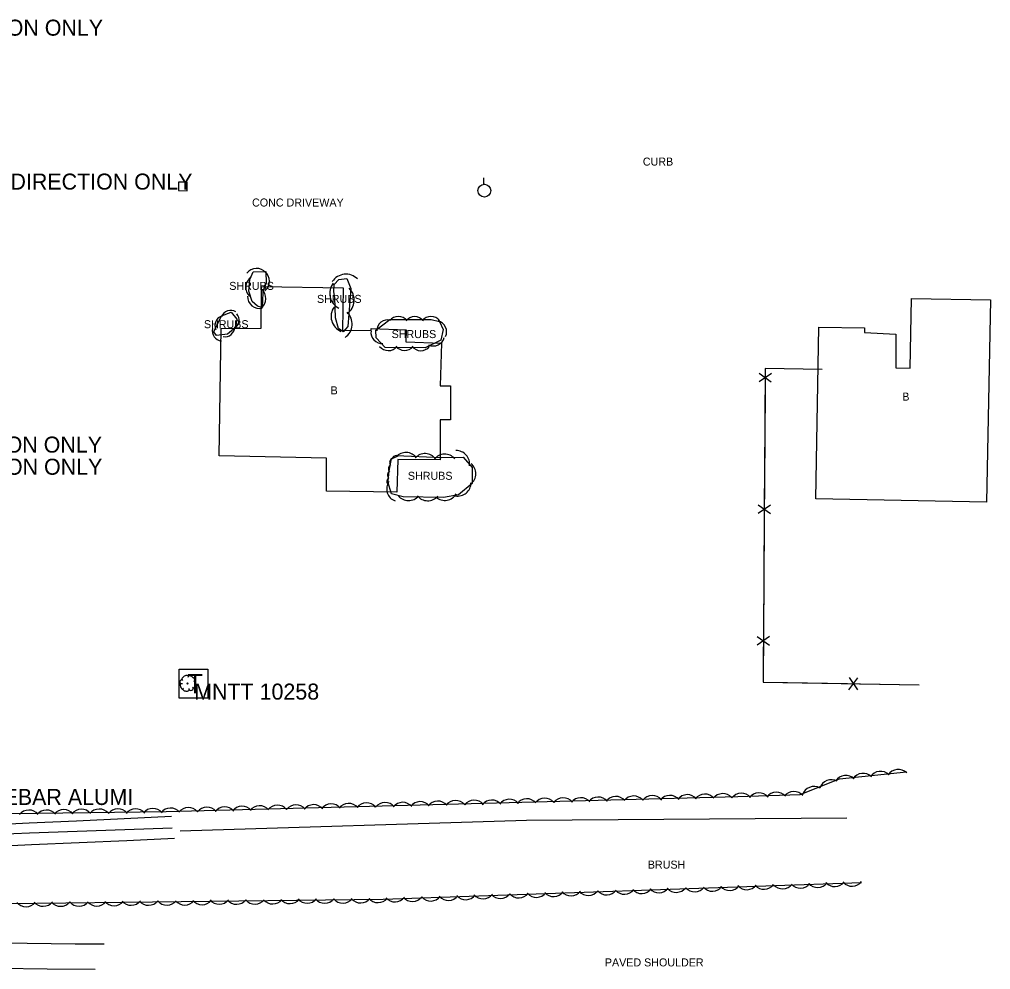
# Model space of a CAD drawing. Extents: x 1802180 to 1804859, y 572524 to 575172.
# Drawn here: x 1804555.9 to 1804859.1, y 573834 to 574130.7 of the extents above; entities that cross this region are included whole.
import ezdxf

# ---------------------------------------------------------------- set-up
doc = ezdxf.new("R2010")
doc.units = 0
for name, color, linetype in [('EX_EDGE_PAVEMENT', 7, 'Continuous'), ('EX_SHOULDER', 7, 'Continuous'), ('S_BUILDING', 7, 'Continuous'), ('S_BUILDING_ANNOT', 7, 'Continuous'), ('S_CURB_ANNOT', 7, 'Continuous'), ('S_DITCHLINE', 7, 'Continuous'), ('S_DRIVEWAY_ANNOT', 7, 'Continuous'), ('S_FENCE', 7, 'Continuous'), ('S_IRON_PIN_ANNOT', 7, 'Continuous'), ('S_MISC_STRUCTURES', 7, 'Continuous'), ('S_SANITARY_SEWER_ANNOT', 7, 'Continuous'), ('S_SHOULDER_ANNOT', 7, 'Continuous'), ('S_STREAM', 7, 'Continuous'), ('S_TELEPHONE_UTILITIES', 7, 'Continuous'), ('S_TELEPHONE_UTILITIES_ANNOT', 7, 'Continuous'), ('S_TREE', 7, 'Continuous'), ('S_TREE_ANNOT', 7, 'Continuous'), ('S_UTILITY_POLE', 7, 'Continuous')]:
    doc.layers.add(name, color=color, linetype=linetype)

msp = doc.modelspace()

# ---------------------------------------------------------------- linework, layer by layer
at = {"layer": 'EX_EDGE_PAVEMENT'}
msp.add_lwpolyline([(1804579.51, 573834.02), (1804564.51, 573834.17), (1804549.51, 573834.32)], dxfattribs=at)
at = {"layer": 'EX_SHOULDER'}
msp.add_lwpolyline([(1804265.55, 573844.85), (1804273.36, 573844.58), (1804288.27, 573844.41), (1804303.25, 573844.37), (1804318.32, 573844.38), (1804333.32, 573844.25), (1804348.29, 573844.14), (1804363.31, 573844.03), (1804378.28, 573843.94), (1804393.31, 573843.88), (1804408.33, 573843.75), (1804423.29, 573843.57), (1804438.35, 573843.38), (1804453.32, 573843.19), (1804468.29, 573843.07), (1804483.29, 573842.96), (1804498.33, 573842.85), (1804513.31, 573842.69), (1804528.29, 573842.53), (1804543.31, 573842.43), (1804558.32, 573842.29), (1804573.31, 573842.11), (1804582.3, 573842.03)], dxfattribs=at)
at = {"layer": 'S_BUILDING'}
for points in [[(1804651.79, 573993.76), (1804618.21, 573994.45), (1804618.82, 574034.25), (1804631.32, 574034.3), (1804631.4, 574047.28), (1804656.97, 574046.95), (1804656.69, 574033.58), (1804665.74, 574033.71), (1804665.69, 574034.22), (1804676.59, 574033.77), (1804676.56, 574029.99), (1804687.61, 574029.63), (1804687.2, 574016.35), (1804690.46, 574016.26), (1804690.44, 574005.65), (1804687.21, 574005.73), (1804687.26, 573993.14), (1804673.98, 573993.25), (1804673.69, 573983.06), (1804651.72, 573983.4), (1804651.79, 573993.76)], [(1804859.1, 574043.14), (1804857.85, 573979.93), (1804804.52, 573981.01), (1804805.42, 574034.61), (1804819.76, 574034.4), (1804819.71, 574032.99), (1804829.54, 574032.44), (1804829.48, 574021.92), (1804833.95, 574021.77), (1804834.43, 574043.6), (1804859.1, 574043.14)]]:
    msp.add_lwpolyline(points, dxfattribs=at)
at = {"layer": 'S_DITCHLINE'}
for points in [[(1804603.31, 573881.86), (1804588.52, 573881.14), (1804573.72, 573880.41), (1804558.93, 573879.69), (1804544.14, 573878.96)], [(1804603.59, 573878.2), (1804588.74, 573877.66), (1804573.9, 573877.12), (1804559.05, 573876.58), (1804544.21, 573876.04)], [(1804604.32, 573874.94), (1804589.41, 573874.27), (1804574.5, 573873.61), (1804559.59, 573872.94), (1804544.68, 573872.27)]]:
    msp.add_lwpolyline(points, dxfattribs=at)
at = {"layer": 'S_FENCE'}
for p, q in [((1804790.65, 574020.19), (1804786.8, 574017.54)), ((1804786.82, 574020.22), (1804790.63, 574017.51)), ((1804790.36, 573979.08), (1804786.51, 573976.43)), ((1804786.53, 573979.11), (1804790.34, 573976.4)), ((1804790.06, 573937.98), (1804786.22, 573935.33)), ((1804786.24, 573938), (1804790.04, 573935.3)), ((1804814.89, 573921.38), (1804817.64, 573925.16)), ((1804814.96, 573925.2), (1804817.57, 573921.33))]:
    msp.add_line(p, q, dxfattribs=at)
for points in [[(1804806.48, 574021.41), (1804788.74, 574021.68), (1804788.05, 573923.77), (1804836.82, 573922.9)], [(1804806.48, 574021.41), (1804788.74, 574021.68), (1804788.74, 574020.73)], [(1804788.71, 574016.99), (1804788.58, 573998.31)], [(1804788.58, 573998.31), (1804788.45, 573979.63)], [(1804788.42, 573975.89), (1804788.29, 573957.2)], [(1804788.29, 573957.2), (1804788.15, 573938.52)], [(1804788.13, 573934.78), (1804788.05, 573923.77), (1804795.72, 573923.63)], [(1804795.72, 573923.63), (1804814.4, 573923.3)], [(1804818.14, 573923.23), (1804836.82, 573922.9)]]:
    msp.add_lwpolyline(points, dxfattribs=at)
at = {"layer": 'S_MISC_STRUCTURES'}
msp.add_lwpolyline([(1804605.58, 574079.93), (1804605.51, 574077.29), (1804608.25, 574077.18), (1804608.28, 574079.85), (1804605.58, 574079.93)], dxfattribs=at)
at = {"layer": 'S_STREAM'}
msp.add_lwpolyline([(1804814.26, 573881.26), (1804714.21, 573880.53), (1804606.01, 573877.25)], dxfattribs=at)
at = {"layer": 'S_TELEPHONE_UTILITIES'}
msp.add_lwpolyline([(1804605.7, 573918.81), (1804605.7, 573927.81), (1804614.7, 573927.81), (1804614.7, 573918.81)], close=True, dxfattribs=at)
at = {"layer": 'S_TREE'}
for p, q in [((1804606.18, 573923.3), (1804606.8, 573923.3)), ((1804606.54, 573924.58), (1804606.82, 573924.26)), ((1804608.64, 573925.7), (1804608.42, 573925.23)), ((1804610.6, 573924.16), (1804610.24, 573924.01)), ((1804606.82, 573921.55), (1804607.08, 573921.93)), ((1804608.85, 573921.4), (1804608.81, 573921.83)), ((1804610.18, 573921.89), (1804609.92, 573922.13))]:
    msp.add_line(p, q, dxfattribs=at)
for points in [[(1804632.83, 574051.97), (1804632.88, 574048.36), (1804631.89, 574045.87), (1804631.77, 574042.58), (1804631.58, 574040.75), (1804630.23, 574041.21), (1804628.54, 574042.59), (1804627.53, 574045.86), (1804627.8, 574049.53), (1804628.84, 574051.86), (1804632.83, 574051.97)], [(1804659.29, 574046.74), (1804658.43, 574034.87), (1804656.9, 574033.13), (1804655.48, 574034.19), (1804654.52, 574037.57), (1804654.38, 574043.87), (1804653.98, 574045.64), (1804654.1, 574047.96), (1804655.64, 574049.54), (1804658.12, 574049.79), (1804659.29, 574046.74)], [(1804618.91, 574038.2), (1804622.02, 574039.27), (1804623.77, 574037.14), (1804623.32, 574034.49), (1804620.88, 574032.46), (1804617.43, 574031.98), (1804616.56, 574033.21), (1804618.91, 574038.2)], [(1804671.49, 574037.05), (1804684.47, 574037.02), (1804687.01, 574036.35), (1804688.18, 574033.94), (1804687.47, 574030.54), (1804682.5, 574028.21), (1804670.11, 574028.25), (1804667.26, 574031.28), (1804667.12, 574033.65), (1804671.49, 574037.05)], [(1804673.49, 573994.53), (1804687.77, 573993.87), (1804694.45, 573994.01), (1804697.24, 573990.82), (1804697.2, 573985.76), (1804692.94, 573982.25), (1804688.32, 573981.43), (1804675.66, 573981.63), (1804672.04, 573982.61), (1804670.86, 573986.31)], [(1804670.87, 573985.44), (1804671.29, 573989.76), (1804672.05, 573993.49), (1804674.08, 573994.48)], [(1804472.42, 573881.72), (1804601.66, 573883.39), (1804780.13, 573888.04), (1804799.65, 573888.65), (1804811.97, 573893.53), (1804832.87, 573895.78)], [(1804818.84, 573861.13), (1804669.43, 573855.95), (1804489.16, 573853.83)]]:
    msp.add_lwpolyline(points, dxfattribs=at)
msp.add_circle((1804608.33, 573923.35), 0.188, dxfattribs=at)
for centre, radius, start, end in [((1804629.91, 574049.1), 3.87, 40.7767, 142.3736), ((1804630.05, 574048.93), 3.87, 310.0027, 51.5996), ((1804657.8, 574046.05), 5.11, 44.9726, 146.5695), ((1804630.41, 574047.09), 3.87, 124.9603, 226.5572), ((1804657.86, 574045.17), 5.11, 141.9789, 243.5758), ((1804628.91, 574043.6), 3.87, 307.1872, 48.7841), ((1804655.28, 574043.05), 5.11, 305.0667, 46.6636), ((1804630.92, 574044.3), 3.87, 180.0159, 281.6128), ((1804621.84, 574036.87), 3.02, 58.1409, 159.7378), ((1804621.42, 574036.8), 3.02, 299.595, 41.1919), ((1804658.29, 574037.98), 5.11, 145.1038, 246.7008), ((1804654.64, 574035.59), 5.11, 305.0667, 46.6636), ((1804619.88, 574035.15), 3.02, 103.9379, 205.5348), ((1804670.9, 574033.4), 3.49, 77.0945, 178.6914), ((1804674.19, 574034.49), 3.49, 39.0519, 140.6489), ((1804679.29, 574034.41), 3.49, 39.0519, 140.6489), ((1804684.35, 574034.47), 3.49, 39.0519, 140.6489), ((1804685.77, 574033.15), 3.49, 335.0197, 76.6166), ((1804619.11, 574033.39), 3.02, 164.8273, 266.4242), ((1804620.05, 574034.65), 3.02, 258.8141, 0.411), ((1804669.1, 574033), 3.49, 172.3764, 273.9733), ((1804685.14, 574032.23), 3.49, 244.3073, 345.9042), ((1804671.04, 574030.79), 3.49, 219.0065, 320.6034), ((1804676.1, 574030.85), 3.49, 219.0065, 320.6034), ((1804681.2, 574030.76), 3.49, 219.0065, 320.6034), ((1804692.3, 573991.98), 4.1, 350.3673, 91.9643), ((1804672.86, 573992.39), 1.4, 117.7379, 219.3348), ((1804673.55, 573993.1), 1.4, 65.349, 166.9459), ((1804676.52, 573991.39), 4.1, 36.5477, 138.1446), ((1804682.51, 573991.03), 4.1, 36.5477, 138.1446), ((1804688.66, 573990.89), 4.1, 40.4649, 142.0618), ((1804672.46, 573990.38), 1.4, 117.7379, 219.3348), ((1804694.26, 573988.84), 4.1, 308.7838, 50.3808), ((1804671.99, 573986.43), 1.4, 123.5839, 225.1808), ((1804672.22, 573988.47), 1.4, 123.5839, 225.1808), ((1804674.64, 573984.18), 4.1, 146.9303, 248.5272), ((1804692.76, 573985.98), 4.1, 258.6625, 0.2594), ((1804677.37, 573984.56), 4.1, 218.2966, 319.8936), ((1804683.34, 573984.51), 4.1, 218.2966, 319.8936), ((1804688.68, 573984.62), 4.1, 229.2489, 330.8458), ((1804824.7, 573892.18), 3.75, 45.3301, 146.927), ((1804830.27, 573892.78), 3.75, 45.3301, 146.927), ((1804809.37, 573889.55), 3.75, 60.8313, 162.4283), ((1804813.87, 573890.9), 3.75, 45.3301, 146.927), ((1804819.27, 573891.56), 3.75, 45.3301, 146.927), ((1804803.95, 573887.44), 3.75, 60.8313, 162.4283), ((1804686.45, 573882.89), 3.75, 40.6941, 142.291), ((1804692.05, 573883.04), 3.75, 40.6941, 142.291), ((1804697.87, 573883.15), 3.75, 40.6941, 142.291), ((1804703.36, 573883.22), 3.75, 40.6941, 142.291), ((1804708.8, 573883.44), 3.75, 40.6941, 142.291), ((1804714.26, 573883.62), 3.75, 40.6941, 142.291), ((1804719.86, 573883.76), 3.75, 40.6941, 142.291), ((1804725.67, 573883.88), 3.75, 40.6941, 142.291), ((1804731.17, 573883.95), 3.75, 40.6941, 142.291), ((1804736.6, 573884.16), 3.75, 40.6941, 142.291), ((1804742.06, 573884.34), 3.75, 40.6941, 142.291), ((1804747.66, 573884.48), 3.75, 40.6941, 142.291), ((1804753.48, 573884.6), 3.75, 40.6941, 142.291), ((1804758.97, 573884.67), 3.75, 40.6941, 142.291), ((1804764.41, 573884.89), 3.75, 40.6941, 142.291), ((1804769.87, 573885.07), 3.75, 40.6941, 142.291), ((1804775.47, 573885.21), 3.75, 40.6941, 142.291), ((1804781.3, 573885.33), 3.75, 40.9906, 142.5875), ((1804786.79, 573885.43), 3.75, 40.9906, 142.5875), ((1804792.22, 573885.67), 3.75, 40.9906, 142.5875), ((1804797.68, 573885.88), 3.75, 40.9906, 142.5875), ((1804558.8, 573880.09), 3.75, 39.9431, 141.54), ((1804564.29, 573880.09), 3.75, 39.9431, 141.54), ((1804569.73, 573880.23), 3.75, 39.9431, 141.54), ((1804575.19, 573880.34), 3.75, 39.9431, 141.54), ((1804580.79, 573880.41), 3.75, 39.9431, 141.54), ((1804586.61, 573880.45), 3.75, 39.9431, 141.54), ((1804592.1, 573880.45), 3.75, 39.9431, 141.54), ((1804597.54, 573880.59), 3.75, 39.9431, 141.54), ((1804603.04, 573880.72), 3.75, 40.6941, 142.291), ((1804608.64, 573880.86), 3.75, 40.6941, 142.291), ((1804614.45, 573880.98), 3.75, 40.6941, 142.291), ((1804619.95, 573881.05), 3.75, 40.6941, 142.291), ((1804625.38, 573881.26), 3.75, 40.6941, 142.291), ((1804630.84, 573881.44), 3.75, 40.6941, 142.291), ((1804636.44, 573881.59), 3.75, 40.6941, 142.291), ((1804642.26, 573881.7), 3.75, 40.6941, 142.291), ((1804647.75, 573881.77), 3.75, 40.6941, 142.291), ((1804653.19, 573881.99), 3.75, 40.6941, 142.291), ((1804658.65, 573882.17), 3.75, 40.6941, 142.291), ((1804664.25, 573882.31), 3.75, 40.6941, 142.291), ((1804670.06, 573882.43), 3.75, 40.6941, 142.291), ((1804675.56, 573882.5), 3.75, 40.6941, 142.291), ((1804680.99, 573882.71), 3.75, 40.6941, 142.291), ((1804755.52, 573861.72), 3.71, 221.1883, 322.7853), ((1804760.95, 573861.84), 3.71, 221.1883, 322.7853), ((1804766.69, 573862), 3.71, 221.1883, 322.7853), ((1804772.22, 573862.19), 3.71, 221.1883, 322.7853), ((1804777.61, 573862.41), 3.71, 221.1883, 322.7853), ((1804782.98, 573862.67), 3.71, 221.1883, 322.7853), ((1804788.41, 573862.79), 3.71, 221.1883, 322.7853), ((1804794.15, 573862.95), 3.71, 221.1883, 322.7853), ((1804799.69, 573863.14), 3.71, 221.1883, 322.7853), ((1804805.08, 573863.37), 3.71, 221.1883, 322.7853), ((1804810.45, 573863.63), 3.71, 221.1883, 322.7853), ((1804815.88, 573863.74), 3.71, 221.1883, 322.7853), ((1804667.81, 573858.64), 3.71, 219.8746, 321.4715), ((1804673.12, 573858.86), 3.71, 221.1883, 322.7853), ((1804678.55, 573858.98), 3.71, 221.1883, 322.7853), ((1804684.29, 573859.14), 3.71, 221.1883, 322.7853), ((1804689.83, 573859.33), 3.71, 221.1883, 322.7853), ((1804695.22, 573859.55), 3.71, 221.1883, 322.7853), ((1804700.59, 573859.82), 3.71, 221.1883, 322.7853), ((1804706.01, 573859.93), 3.71, 221.1883, 322.7853), ((1804711.76, 573860.1), 3.71, 221.1883, 322.7853), ((1804717.29, 573860.28), 3.71, 221.1883, 322.7853), ((1804722.68, 573860.51), 3.71, 221.1883, 322.7853), ((1804728.05, 573860.77), 3.71, 221.1883, 322.7853), ((1804733.48, 573860.88), 3.71, 221.1883, 322.7853), ((1804739.22, 573861.05), 3.71, 221.1883, 322.7853), ((1804744.76, 573861.24), 3.71, 221.1883, 322.7853), ((1804750.15, 573861.46), 3.71, 221.1883, 322.7853), ((1804557.89, 573857.35), 3.71, 219.8746, 321.4715), ((1804563.27, 573857.49), 3.71, 219.8746, 321.4715), ((1804568.69, 573857.48), 3.71, 219.8746, 321.4715), ((1804574.44, 573857.51), 3.71, 219.8746, 321.4715), ((1804579.98, 573857.57), 3.71, 219.8746, 321.4715), ((1804585.37, 573857.67), 3.71, 219.8746, 321.4715), ((1804590.75, 573857.81), 3.71, 219.8746, 321.4715), ((1804596.17, 573857.8), 3.71, 219.8746, 321.4715), ((1804601.92, 573857.83), 3.71, 219.8746, 321.4715), ((1804607.46, 573857.89), 3.71, 219.8746, 321.4715), ((1804612.85, 573857.99), 3.71, 219.8746, 321.4715), ((1804618.23, 573858.13), 3.71, 219.8746, 321.4715), ((1804623.66, 573858.12), 3.71, 219.8746, 321.4715), ((1804629.4, 573858.16), 3.71, 219.8746, 321.4715), ((1804634.94, 573858.22), 3.71, 219.8746, 321.4715), ((1804640.33, 573858.32), 3.71, 219.8746, 321.4715), ((1804645.71, 573858.45), 3.71, 219.8746, 321.4715), ((1804651.14, 573858.44), 3.71, 219.8746, 321.4715), ((1804656.88, 573858.48), 3.71, 219.8746, 321.4715), ((1804662.42, 573858.54), 3.71, 219.8746, 321.4715)]:
    msp.add_arc(centre, radius, start, end, dxfattribs=at)
for centre, major_axis, ratio, start_param, end_param in [((1804606.36, 573923.95), (0.168, 0.567), 0.646762, 0, 3.141593), ((1804606.53, 573922.49), (-0.337, 0.88), 0.420543, 6.283185, 9.424777), ((1804607.59, 573925.12), (1.02, 0.6), 0.471018, 0, 3.141593), ((1804609.61, 573924.94), (-1, 0.75), 0.405113, 3.141593, 6.283186), ((1804610.36, 573923.06), (0.25, 1.13), 0.482994, 3.141593, 6.283185), ((1804607.89, 573921.51), (-1.01, 0.11), 0.529943, 0, 3.141593), ((1804609.52, 573921.67), (0.602, 0.255), 0.711534, 3.141592, 6.283185)]:
    msp.add_ellipse(centre, major_axis=major_axis, ratio=ratio, start_param=start_param, end_param=end_param, dxfattribs=at)
at = {"layer": 'S_UTILITY_POLE'}
msp.add_line((1804700.91, 574079.27), (1804700.91, 574081.26), dxfattribs=at)
msp.add_circle((1804701.03, 574077.26), 2, dxfattribs=at)

# ---------------------------------------------------------------- texts
at = {"layer": 'S_BUILDING_ANNOT'}
for p in [(1804653.02, 574013.64), (1804831.54, 574011.68)]:
    msp.add_text('B', height=2.5, dxfattribs=at).set_placement(p)
at = {"layer": 'S_CURB_ANNOT'}
msp.add_text('CURB', height=2.5, dxfattribs=at).set_placement((1804750.52, 574085.07))
at = {"layer": 'S_DRIVEWAY_ANNOT'}
msp.add_text('CONC DRIVEWAY', height=2.5, dxfattribs=at).set_placement((1804628.5, 574072.29))
at = {"layer": 'S_IRON_PIN_ANNOT'}
msp.add_text('BOUNDARY MONUMENT / REBAR ALUMI ', height=5, dxfattribs=at).set_placement((1804461.38, 573885.42))
at = {"layer": 'S_SANITARY_SEWER_ANNOT'}
for p in [(1804444.53, 574125.64), (1804472.45, 574077.58), (1804444.2, 573995.45), (1804444.3, 573988.53)]:
    msp.add_text('NATURAL GROUND FOR DIRECTION ONLY    ', height=5, dxfattribs=at).set_placement(p)
at = {"layer": 'S_SHOULDER_ANNOT'}
msp.add_text('PAVED SHOULDER', height=2.5, dxfattribs=at).set_placement((1804738.66, 573835.01))
at = {"layer": 'S_TELEPHONE_UTILITIES'}
msp.add_text('T', height=6, rotation=360, dxfattribs=at).set_placement((1804608.27, 573920.31))
at = {"layer": 'S_TELEPHONE_UTILITIES_ANNOT'}
msp.add_text('MNTT 10258 ', height=5, dxfattribs=at).set_placement((1804610.43, 573918.32))
at = {"layer": 'S_TREE_ANNOT'}
for s, p in [('SHRUBS', (1804621.38, 574046.26)), ('SHRUBS', (1804648.77, 574042.2)), ('SHRUBS', (1804613.47, 574034.3)), ('SHRUBS', (1804672.08, 574031.21)), ('SHRUBS', (1804677.15, 573986.96)), ('BRUSH', (1804752.07, 573865.54))]:
    msp.add_text(s, height=2.5, dxfattribs=at).set_placement(p)

doc.saveas('drawing.dxf')
